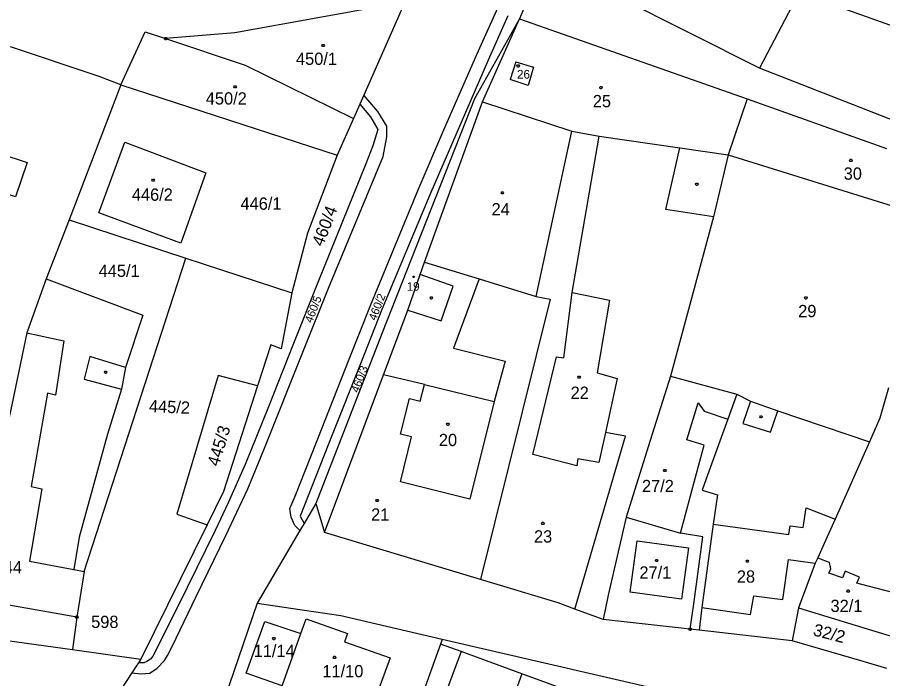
# Model space of a CAD drawing. Extents: x -634640 to -629202, y -1196156 to -1190068.
# Drawn here: x -631593.2 to -631473.2, y -1192521.9 to -1192430.1 of the extents above; entities that cross this region are included whole.
import ezdxf

# ---------------------------------------------------------------- set-up
doc = ezdxf.new("R2010")
doc.units = 0
for name, color, linetype in [('Vrstva 1', 7, 'Continuous'), ('Vrstva 2', 7, 'Continuous'), ('Vrstva 3', 7, 'Continuous'), ('Vrstva 4', 7, 'Continuous'), ('Vrstva 5', 7, 'Continuous'), ('Vrstva 8', 7, 'Continuous')]:
    doc.layers.add(name, color=color, linetype=linetype)

msp = doc.modelspace()

# ---------------------------------------------------------------- linework, layer by layer
at = {"layer": 'Vrstva 1'}
for p, q in [((-631490.28, -1192437.19), (-631513.73, -1192425.4)), ((-631539.49, -1192428.06), (-631563.09, -1192432.29)), ((-631539.49, -1192428.06), (-631545.2, -1192440.97)), ((-631522.44, -1192427.56), (-631523.59, -1192430.36)), ((-631470.93, -1192431.68), (-631480.78, -1192428.21)), ((-631529.49, -1192435.33), (-631526.57, -1192428.73)), ((-631485.75, -1192428.57), (-631490.28, -1192437.19)), ((-631523.59, -1192430.36), (-631529.85, -1192441.45)), ((-631528.71, -1192441.87), (-631523.59, -1192430.36)), ((-631525.2, -1192429.94), (-631527.92, -1192436.1)), ((-631523.59, -1192430.36), (-631492.01, -1192441.47)), ((-631563.09, -1192432.29), (-631572.7, -1192433.11)), ((-631581.89, -1192438.36), (-631594.19, -1192434.24)), ((-631534.08, -1192445.78), (-631529.49, -1192435.33)), ((-631527.92, -1192436.1), (-631536.04, -1192454.76)), ((-631524.11, -1192436.33), (-631524.88, -1192438.77)), ((-631524.11, -1192436.33), (-631521.67, -1192437.06)), ((-631521.67, -1192437.06), (-631522.4, -1192439.59)), ((-631456.75, -1192450.33), (-631490.28, -1192437.19)), ((-631578.89, -1192439.52), (-631581.89, -1192438.36)), ((-631522.4, -1192439.59), (-631524.88, -1192438.77)), ((-631578.89, -1192439.52), (-631586.04, -1192458.23)), ((-631578.89, -1192439.52), (-631548.87, -1192449.26)), ((-631545.2, -1192440.97), (-631545.75, -1192442.2)), ((-631543.24, -1192443.21), (-631545.2, -1192440.97)), ((-631545.75, -1192442.2), (-631546.62, -1192444.18)), ((-631545.75, -1192442.2), (-631544.26, -1192443.94)), ((-631529.85, -1192441.45), (-631542.64, -1192473.89)), ((-631536.75, -1192464.13), (-631528.71, -1192441.87)), ((-631528.71, -1192441.87), (-631516.35, -1192445.93)), ((-631492.01, -1192441.47), (-631494.64, -1192449.21)), ((-631492.01, -1192441.47), (-631472.67, -1192448.35)), ((-631541.98, -1192445.24), (-631543.24, -1192443.21)), ((-631546.62, -1192444.18), (-631548.87, -1192449.26)), ((-631544.26, -1192443.94), (-631543.25, -1192445.71)), ((-631543.25, -1192445.71), (-631543.95, -1192447.98)), ((-631542, -1192446.72), (-631541.98, -1192445.24)), ((-631537.66, -1192454.07), (-631534.08, -1192445.78)), ((-631521.26, -1192468.88), (-631516.35, -1192445.93)), ((-631516.35, -1192445.93), (-631512.53, -1192446.63)), ((-631542.51, -1192449.47), (-631542, -1192446.72)), ((-631516.28, -1192468.3), (-631512.53, -1192446.63)), ((-631512.53, -1192446.63), (-631501.33, -1192448.25)), ((-631581.93, -1192457.26), (-631578.31, -1192447.49)), ((-631578.31, -1192447.49), (-631567.08, -1192451.74)), ((-631543.95, -1192447.98), (-631544.92, -1192450.46)), ((-631501.33, -1192448.25), (-631494.64, -1192449.21)), ((-631548.87, -1192449.26), (-631552.99, -1192460.11)), ((-631550.08, -1192467.72), (-631542.51, -1192449.47)), ((-631494.64, -1192449.21), (-631496.68, -1192457.84)), ((-631494.64, -1192449.21), (-631462.58, -1192459.22)), ((-631544.92, -1192450.46), (-631551.55, -1192466.95)), ((-631567.08, -1192451.74), (-631570.56, -1192461.49)), ((-631544.24, -1192470.11), (-631537.66, -1192454.07)), ((-631536.04, -1192454.76), (-631542.7, -1192470.66)), ((-631586.04, -1192458.23), (-631589.23, -1192466.42)), ((-631586.04, -1192458.23), (-631569.85, -1192463.55)), ((-631570.56, -1192461.49), (-631581.93, -1192457.26)), ((-631496.68, -1192457.84), (-631502.65, -1192479.92)), ((-631552.99, -1192460.11), (-631555.16, -1192468.38)), ((-631583.95, -1192507.01), (-631569.85, -1192463.55)), ((-631569.85, -1192463.55), (-631555.16, -1192468.38)), ((-631537.37, -1192465.81), (-631536.75, -1192464.13)), ((-631536.75, -1192464.13), (-631529.19, -1192466.44)), ((-631589.23, -1192466.42), (-631591.94, -1192473.9)), ((-631589.23, -1192466.42), (-631575.84, -1192471.45)), ((-631539.1, -1192470.75), (-631537.37, -1192465.81)), ((-631529.19, -1192466.44), (-631532.74, -1192476.05)), ((-631529.19, -1192466.44), (-631521.26, -1192468.88)), ((-631551.55, -1192466.95), (-631555.01, -1192475.6)), ((-631553.45, -1192476.15), (-631550.08, -1192467.72)), ((-631555.16, -1192468.38), (-631556.66, -1192476.13)), ((-631521.26, -1192468.88), (-631519.36, -1192469.23)), ((-631517.46, -1192477.39), (-631516.28, -1192468.3)), ((-631547.2, -1192477.58), (-631544.24, -1192470.11)), ((-631519.36, -1192469.23), (-631528.98, -1192508.12)), ((-631575.84, -1192471.45), (-631578.23, -1192478.72)), ((-631542.7, -1192470.66), (-631545.65, -1192478.19)), ((-631542.46, -1192479.76), (-631539.1, -1192470.75)), ((-631591.94, -1192473.9), (-631599.64, -1192510.8)), ((-631542.64, -1192473.89), (-631551.83, -1192497.57)), ((-631558.1, -1192475.57), (-631559.93, -1192481.26)), ((-631559.04, -1192490.15), (-631553.45, -1192476.15)), ((-631555.01, -1192475.6), (-631558.41, -1192484.16)), ((-631556.66, -1192476.13), (-631558.1, -1192475.57)), ((-631532.74, -1192476.05), (-631525.58, -1192477.83)), ((-631521.76, -1192490.8), (-631518.44, -1192477.22)), ((-631518.44, -1192477.22), (-631517.46, -1192477.39)), ((-631551.05, -1192487.3), (-631547.2, -1192477.58)), ((-631545.65, -1192478.19), (-631549.56, -1192488.05)), ((-631525.58, -1192477.83), (-631527.12, -1192483.43)), ((-631578.23, -1192478.72), (-631578.79, -1192481.72)), ((-631565.39, -1192479.83), (-631571.12, -1192499.08)), ((-631559.93, -1192481.26), (-631565.39, -1192479.83)), ((-631550.62, -1192501.61), (-631542.46, -1192479.76)), ((-631536.77, -1192481.07), (-631542.46, -1192479.76)), ((-631502.65, -1192479.92), (-631505.46, -1192488.86)), ((-631502.65, -1192479.92), (-631493.46, -1192482.43)), ((-631578.79, -1192481.72), (-631580.75, -1192487.98)), ((-631559.93, -1192481.26), (-631564.65, -1192495.94)), ((-631537.35, -1192483.38), (-631536.77, -1192481.07)), ((-631472.4, -1192481.56), (-631473.59, -1192485.73)), ((-631540.1, -1192487.97), (-631538.85, -1192483.02)), ((-631538.85, -1192483.02), (-631537.35, -1192483.38)), ((-631527.12, -1192483.43), (-631530.5, -1192496.97)), ((-631493.46, -1192482.43), (-631494.7, -1192485.9)), ((-631493.46, -1192482.43), (-631491.57, -1192483.4)), ((-631491.57, -1192483.4), (-631487.74, -1192484.75)), ((-631558.41, -1192484.16), (-631561.63, -1192492.19)), ((-631487.74, -1192484.75), (-631475.05, -1192489.01)), ((-631473.59, -1192485.73), (-631475.05, -1192489.01)), ((-631494.7, -1192485.9), (-631497.69, -1192494.16)), ((-631580.75, -1192487.98), (-631584.65, -1192502.24)), ((-631554.7, -1192496.56), (-631551.05, -1192487.3)), ((-631549.56, -1192488.05), (-631554.02, -1192499.34)), ((-631538.57, -1192488.33), (-631540.1, -1192487.97)), ((-631515.9, -1192512.23), (-631508.89, -1192488.24)), ((-631511.68, -1192487.73), (-631512.58, -1192491.9)), ((-631508.89, -1192488.24), (-631511.68, -1192487.73)), ((-631540.11, -1192494.56), (-631538.57, -1192488.33)), ((-631505.46, -1192488.86), (-631508.79, -1192499.48)), ((-631475.05, -1192489.01), (-631479.83, -1192499.76)), ((-631561.29, -1192495.55), (-631559.04, -1192490.15)), ((-631515.65, -1192492.35), (-631521.76, -1192490.8)), ((-631515.49, -1192491.41), (-631515.65, -1192492.35)), ((-631512.58, -1192491.9), (-631515.49, -1192491.41)), ((-631561.63, -1192492.19), (-631563.99, -1192497.47)), ((-631497.69, -1192494.16), (-631498.26, -1192495.72)), ((-631530.5, -1192496.97), (-631540.11, -1192494.56)), ((-631564.65, -1192495.94), (-631566.93, -1192500.56)), ((-631564.32, -1192502.02), (-631561.29, -1192495.55)), ((-631555.46, -1192498.27), (-631554.7, -1192496.56)), ((-631498.26, -1192495.72), (-631496.14, -1192496.39)), ((-631496.14, -1192496.39), (-631496.72, -1192500.46)), ((-631563.99, -1192497.47), (-631565.82, -1192501.31)), ((-631551.83, -1192497.57), (-631553.46, -1192500.34)), ((-631551.83, -1192497.57), (-631550.62, -1192501.61)), ((-631555.27, -1192499.5), (-631555.46, -1192498.27)), ((-631571.12, -1192499.08), (-631566.93, -1192500.56)), ((-631554.75, -1192500.65), (-631555.27, -1192499.5)), ((-631554.02, -1192499.34), (-631553.46, -1192500.34)), ((-631508.79, -1192499.48), (-631511.31, -1192510.28)), ((-631508.79, -1192499.48), (-631501.28, -1192501.7)), ((-631479.83, -1192499.76), (-631481.34, -1192503.14)), ((-631566.93, -1192500.56), (-631576.09, -1192519.16)), ((-631565.82, -1192501.31), (-631570.97, -1192511.89)), ((-631554.05, -1192501.34), (-631559.96, -1192511.39)), ((-631554.05, -1192501.34), (-631554.75, -1192500.65)), ((-631553.46, -1192500.34), (-631554.05, -1192501.34)), ((-631496.72, -1192500.46), (-631498.3, -1192512.01)), ((-631584.65, -1192502.24), (-631585.42, -1192506.74)), ((-631568.43, -1192510.5), (-631564.32, -1192502.02)), ((-631528.98, -1192508.12), (-631550.62, -1192501.61)), ((-631481.34, -1192503.14), (-631482.23, -1192505.14)), ((-631482.56, -1192505.88), (-631484.9, -1192512.07)), ((-631482.23, -1192505.14), (-631482.56, -1192505.88)), ((-631585.42, -1192506.74), (-631583.95, -1192507.01)), ((-631583.95, -1192507.01), (-631585, -1192513.33)), ((-631518.24, -1192511.36), (-631528.98, -1192508.12)), ((-631571.77, -1192517.4), (-631568.43, -1192510.5)), ((-631511.31, -1192510.28), (-631511.98, -1192513.68)), ((-631570.97, -1192511.89), (-631574.43, -1192518.77)), ((-631559.96, -1192511.39), (-631565.82, -1192528.47)), ((-631559.96, -1192511.39), (-631554.07, -1192512.29)), ((-631515.9, -1192512.23), (-631518.24, -1192511.36)), ((-631511.98, -1192513.68), (-631515.9, -1192512.23)), ((-631499.93, -1192515.03), (-631499.35, -1192511.19)), ((-631498.3, -1192512.01), (-631498.69, -1192515.17)), ((-631484.9, -1192512.07), (-631485.75, -1192516.61)), ((-631484.9, -1192512.07), (-631474.77, -1192515.13)), ((-631585, -1192513.33), (-631585.57, -1192517.83)), ((-631554.07, -1192512.29), (-631548.36, -1192513.13)), ((-631548.36, -1192513.13), (-631534.3, -1192516.38)), ((-631561.49, -1192521.13), (-631558.9, -1192513.95)), ((-631558.9, -1192513.95), (-631553.93, -1192515.63)), ((-631553.93, -1192515.63), (-631553.19, -1192513.56)), ((-631553.19, -1192513.56), (-631547.44, -1192515.61)), ((-631499.93, -1192515.03), (-631511.98, -1192513.68)), ((-631600.91, -1192515.76), (-631585.57, -1192517.83)), ((-631556.51, -1192522.86), (-631553.93, -1192515.63)), ((-631547.44, -1192515.61), (-631547.85, -1192516.75)), ((-631498.69, -1192515.17), (-631499.93, -1192515.03)), ((-631485.75, -1192516.61), (-631498.69, -1192515.17)), ((-631474.77, -1192515.13), (-631471.87, -1192516.01)), ((-631547.85, -1192516.75), (-631541.51, -1192519)), ((-631534.3, -1192516.38), (-631534.56, -1192517.11)), ((-631534.3, -1192516.38), (-631497.57, -1192524.88)), ((-631476.38, -1192519.35), (-631485.75, -1192516.61)), ((-631585.57, -1192517.83), (-631576.09, -1192519.16)), ((-631572.41, -1192518.66), (-631571.77, -1192517.4)), ((-631534.56, -1192517.11), (-631541.55, -1192536.43)), ((-631531.67, -1192518.13), (-631536.24, -1192530.34)), ((-631531.67, -1192518.13), (-631534.56, -1192517.11)), ((-631523.28, -1192521.21), (-631531.67, -1192518.13)), ((-631576.09, -1192519.16), (-631576.44, -1192519.7)), ((-631574.78, -1192519.17), (-631575.26, -1192519.51)), ((-631574.43, -1192518.77), (-631574.78, -1192519.17)), ((-631573.87, -1192520.42), (-631572.83, -1192519.35)), ((-631572.83, -1192519.35), (-631572.41, -1192518.66)), ((-631541.51, -1192519), (-631544.51, -1192527.15)), ((-631472.64, -1192520.48), (-631476.38, -1192519.35)), ((-631576.75, -1192520.16), (-631577.34, -1192521.05)), ((-631576.44, -1192519.7), (-631576.75, -1192520.16)), ((-631575.69, -1192519.66), (-631576.44, -1192519.7)), ((-631575.26, -1192519.51), (-631575.69, -1192519.66)), ((-631574.86, -1192521.11), (-631573.87, -1192520.42)), ((-631577.34, -1192521.05), (-631580.95, -1192526.53)), ((-631577.34, -1192521.05), (-631576.05, -1192521.2)), ((-631576.05, -1192521.2), (-631574.86, -1192521.11)), ((-631556.51, -1192522.86), (-631561.49, -1192521.13)), ((-631523.28, -1192521.21), (-631527.71, -1192533.42)), ((-631515.39, -1192524.08), (-631523.28, -1192521.21))]:
    msp.add_line(p, q, dxfattribs=at)
for points in [[(-631578.89, -1192439.52), (-631575.53, -1192432.16), (-631572.7, -1192433.11)], [(-631572.7, -1192433.11), (-631561.66, -1192436.8), (-631546.62, -1192444.18)], [(-631597.29, -1192453.81), (-631595.7, -1192449.03), (-631591.88, -1192450.3), (-631593.51, -1192455.07), (-631597.29, -1192453.81)], [(-631499.35, -1192511.19), (-631498.15, -1192502.2), (-631501.28, -1192501.7)]]:
    msp.add_lwpolyline(points, dxfattribs=at)
at = {"layer": 'Vrstva 3'}
for points in [[(-631550.75, -1192433.9), (-631550.66, -1192434.05), (-631550.75, -1192434.2), (-631550.93, -1192434.2), (-631551.02, -1192434.05), (-631550.93, -1192433.9), (-631550.75, -1192433.9)], [(-631562.95, -1192439.65), (-631562.86, -1192439.8), (-631562.95, -1192439.95), (-631563.13, -1192439.95), (-631563.22, -1192439.8), (-631563.13, -1192439.65), (-631562.95, -1192439.65)], [(-631512.2, -1192439.75), (-631512.11, -1192439.9), (-631512.2, -1192440.05), (-631512.38, -1192440.05), (-631512.47, -1192439.9), (-631512.38, -1192439.75), (-631512.2, -1192439.75)], [(-631477.53, -1192449.84), (-631477.44, -1192449.99), (-631477.53, -1192450.14), (-631477.71, -1192450.14), (-631477.8, -1192449.99), (-631477.71, -1192449.84), (-631477.53, -1192449.84)], [(-631525.88, -1192454.34), (-631525.79, -1192454.49), (-631525.88, -1192454.64), (-631526.06, -1192454.64), (-631526.15, -1192454.49), (-631526.06, -1192454.34), (-631525.88, -1192454.34)], [(-631538.22, -1192466.05), (-631538.159, -1192466.15), (-631538.22, -1192466.25), (-631538.34, -1192466.25), (-631538.401, -1192466.15), (-631538.34, -1192466.05), (-631538.22, -1192466.05)], [(-631483.78, -1192468.92), (-631483.69, -1192469.07), (-631483.78, -1192469.22), (-631483.96, -1192469.22), (-631484.05, -1192469.07), (-631483.96, -1192468.92), (-631483.78, -1192468.92)], [(-631543.26, -1192497.02), (-631543.17, -1192497.17), (-631543.26, -1192497.32), (-631543.44, -1192497.32), (-631543.53, -1192497.17), (-631543.44, -1192497.02), (-631543.26, -1192497.02)], [(-631520.25, -1192500.19), (-631520.16, -1192500.34), (-631520.25, -1192500.49), (-631520.43, -1192500.49), (-631520.52, -1192500.34), (-631520.43, -1192500.19), (-631520.25, -1192500.19)]]:
    msp.add_lwpolyline(points, dxfattribs=at)
at = {"layer": 'Vrstva 4'}
for p, q in [((-631503.28, -1192456.81), (-631501.33, -1192448.25)), ((-631496.68, -1192457.84), (-631503.28, -1192456.81)), ((-631532.79, -1192467.44), (-631537.37, -1192465.81)), ((-631534.45, -1192472.23), (-631532.79, -1192467.44)), ((-631516.28, -1192468.3), (-631511.1, -1192469.39)), ((-631511.1, -1192469.39), (-631512.8, -1192479.48)), ((-631539.1, -1192470.75), (-631534.45, -1192472.23)), ((-631591.94, -1192473.9), (-631586.78, -1192475.03)), ((-631586.78, -1192475.03), (-631587.93, -1192482.54)), ((-631583.19, -1192477.19), (-631583.98, -1192480.33)), ((-631578.23, -1192478.72), (-631583.19, -1192477.19)), ((-631512.8, -1192479.48), (-631510.05, -1192480.23)), ((-631583.98, -1192480.33), (-631578.79, -1192481.72)), ((-631510.05, -1192480.23), (-631511.68, -1192487.73)), ((-631536.77, -1192481.07), (-631527.12, -1192483.43)), ((-631589.04, -1192482.26), (-631591.32, -1192495.24)), ((-631587.93, -1192482.54), (-631589.04, -1192482.26)), ((-631491.57, -1192483.4), (-631492.63, -1192486.49)), ((-631500.38, -1192488.76), (-631498.83, -1192483.63)), ((-631498.83, -1192483.63), (-631497.96, -1192484.8)), ((-631497.96, -1192484.8), (-631494.7, -1192485.9)), ((-631488.76, -1192487.68), (-631487.74, -1192484.75)), ((-631492.63, -1192486.49), (-631488.76, -1192487.68)), ((-631497.98, -1192489.49), (-631500.38, -1192488.76)), ((-631499.18, -1192493.95), (-631497.98, -1192489.49)), ((-631501.28, -1192501.7), (-631499.18, -1192493.95)), ((-631591.32, -1192495.24), (-631589.86, -1192495.55)), ((-631589.86, -1192495.55), (-631591.54, -1192505.59)), ((-631484.24, -1192500.9), (-631483.81, -1192498.2)), ((-631483.81, -1192498.2), (-631479.83, -1192499.76)), ((-631496.72, -1192500.46), (-631486.23, -1192501.9)), ((-631486.23, -1192501.9), (-631486.05, -1192500.7)), ((-631486.05, -1192500.7), (-631484.24, -1192500.9)), ((-631591.54, -1192505.59), (-631585.42, -1192506.74)), ((-631487.07, -1192510.9), (-631486.28, -1192505.37)), ((-631486.28, -1192505.37), (-631482.56, -1192505.88)), ((-631481.59, -1192505.38), (-631482.23, -1192505.14)), ((-631476.29, -1192508.78), (-631476.78, -1192508.65)), ((-631470.36, -1192510.33), (-631476.29, -1192508.78)), ((-631585, -1192513.33), (-631599.64, -1192510.8)), ((-631491.54, -1192513), (-631491.08, -1192510.39)), ((-631491.08, -1192510.39), (-631487.07, -1192510.9)), ((-631498.3, -1192512.01), (-631491.54, -1192513))]:
    msp.add_line(p, q, dxfattribs=at)
for points in [[(-631500.13, -1192503.72), (-631501.12, -1192510.84), (-631508.23, -1192509.86), (-631507.28, -1192502.74), (-631500.13, -1192503.72)], [(-631480.67, -1192507.26), (-631480.42, -1192506.65), (-631480.59, -1192505.76), (-631481.59, -1192505.38)], [(-631478.43, -1192506.96), (-631478.77, -1192507.9), (-631480.67, -1192507.26)], [(-631476.78, -1192508.65), (-631476.41, -1192507.78), (-631478.43, -1192506.96)]]:
    msp.add_lwpolyline(points, dxfattribs=at)
at = {"layer": 'Vrstva 5'}
for points in [[(-631523.67, -1192436.75), (-631523.58, -1192436.9), (-631523.67, -1192437.05), (-631523.85, -1192437.05), (-631523.94, -1192436.9), (-631523.85, -1192436.75), (-631523.67, -1192436.75)], [(-631574.3, -1192452.58), (-631574.21, -1192452.73), (-631574.3, -1192452.88), (-631574.48, -1192452.88), (-631574.57, -1192452.73), (-631574.48, -1192452.58), (-631574.3, -1192452.58)], [(-631498.92, -1192453.16), (-631498.83, -1192453.31), (-631498.92, -1192453.46), (-631499.1, -1192453.46), (-631499.19, -1192453.31), (-631499.1, -1192453.16), (-631498.92, -1192453.16)], [(-631535.73, -1192468.92), (-631535.64, -1192469.07), (-631535.73, -1192469.22), (-631535.91, -1192469.22), (-631536, -1192469.07), (-631535.91, -1192468.92), (-631535.73, -1192468.92)], [(-631580.9, -1192479.23), (-631580.81, -1192479.38), (-631580.9, -1192479.53), (-631581.08, -1192479.53), (-631581.17, -1192479.38), (-631581.08, -1192479.23), (-631580.9, -1192479.23)], [(-631515.24, -1192479.92), (-631515.15, -1192480.07), (-631515.24, -1192480.22), (-631515.42, -1192480.22), (-631515.51, -1192480.07), (-631515.42, -1192479.92), (-631515.24, -1192479.92)], [(-631490, -1192485.42), (-631489.91, -1192485.57), (-631490, -1192485.72), (-631490.18, -1192485.72), (-631490.27, -1192485.57), (-631490.18, -1192485.42), (-631490, -1192485.42)], [(-631533.43, -1192486.45), (-631533.34, -1192486.6), (-631533.43, -1192486.75), (-631533.61, -1192486.75), (-631533.7, -1192486.6), (-631533.61, -1192486.45), (-631533.43, -1192486.45)], [(-631503.34, -1192492.86), (-631503.25, -1192493.01), (-631503.34, -1192493.16), (-631503.52, -1192493.16), (-631503.61, -1192493.01), (-631503.52, -1192492.86), (-631503.34, -1192492.86)], [(-631504.48, -1192505.33), (-631504.39, -1192505.48), (-631504.48, -1192505.63), (-631504.66, -1192505.63), (-631504.75, -1192505.48), (-631504.66, -1192505.33), (-631504.48, -1192505.33)], [(-631491.9, -1192505.44), (-631491.81, -1192505.59), (-631491.9, -1192505.74), (-631492.08, -1192505.74), (-631492.17, -1192505.59), (-631492.08, -1192505.44), (-631491.9, -1192505.44)], [(-631477.91, -1192509.58), (-631477.82, -1192509.73), (-631477.91, -1192509.88), (-631478.09, -1192509.88), (-631478.18, -1192509.73), (-631478.09, -1192509.58), (-631477.91, -1192509.58)], [(-631557.57, -1192516.17), (-631557.48, -1192516.32), (-631557.57, -1192516.47), (-631557.75, -1192516.47), (-631557.84, -1192516.32), (-631557.75, -1192516.17), (-631557.57, -1192516.17)], [(-631549.15, -1192518.78), (-631549.06, -1192518.93), (-631549.15, -1192519.08), (-631549.33, -1192519.08), (-631549.42, -1192518.93), (-631549.33, -1192518.78), (-631549.15, -1192518.78)]]:
    msp.add_lwpolyline(points, dxfattribs=at)
at = {"layer": 'Vrstva 8'}
for points in [[(-631572.61, -1192432.96), (-631572.52, -1192433.11), (-631572.61, -1192433.26), (-631572.79, -1192433.26), (-631572.88, -1192433.11), (-631572.79, -1192432.96), (-631572.61, -1192432.96)], [(-631584.91, -1192513.18), (-631584.82, -1192513.33), (-631584.91, -1192513.48), (-631585.09, -1192513.48), (-631585.18, -1192513.33), (-631585.09, -1192513.18), (-631584.91, -1192513.18)], [(-631499.84, -1192514.88), (-631499.75, -1192515.03), (-631499.84, -1192515.18), (-631500.02, -1192515.18), (-631500.11, -1192515.03), (-631500.02, -1192514.88), (-631499.84, -1192514.88)]]:
    msp.add_lwpolyline(points, dxfattribs=at)

# ---------------------------------------------------------------- texts
at = {"layer": 'Vrstva 2'}
for s, height, p in [('450/1', 1.7, (-631554.594, -1192436.75)), ('26', 1.2, (-631523.932, -1192438.65)), ('450/2', 1.7, (-631567.102, -1192442.25)), ('25', 1.7, (-631513.423, -1192442.62)), ('30', 1.7, (-631478.623, -1192452.67)), ('446/2', 1.7, (-631577.363, -1192455.59)), ('446/1', 1.7, (-631562.293, -1192456.84)), ('24', 1.7, (-631527.463, -1192457.62)), ('445/1', 1.7, (-631581.963, -1192466.16)), ('19', 1.19, (-631539.225, -1192468.08)), ('29', 1.7, (-631484.933, -1192471.74)), ('22', 1.7, (-631516.503, -1192483.07)), ('20', 1.7, (-631534.773, -1192489.62)), ('27/2', 1.7, (-631506.605, -1192496.01)), ('21', 1.7, (-631544.173, -1192499.96)), ('23', 1.7, (-631521.583, -1192503)), ('444', 1.7, (-631596.393, -1192507.28)), ('27/1', 1.7, (-631506.957, -1192508)), ('28', 1.7, (-631493.443, -1192508.56)), ('32/1', 1.7, (-631480.453, -1192512.63)), ('11/14', 1.7, (-631560.464, -1192518.88)), ('11/10', 1.7, (-631550.937, -1192521.69))]:
    msp.add_text(s, height=height, dxfattribs=at).set_placement(p)
for s, height, rotation, p in [('460/4', 1.7, 68.86953, (-631550.864, -1192462.039)), ('460/5', 1.14, 68.86953, (-631552.373, -1192472.622)), ('460/2', 1.14, 68.86953, (-631543.513, -1192472.302)), ('460/3', 1.14, 68.86953, (-631545.943, -1192482.302)), ('445/2', 1.7, 357.58296, (-631575.013, -1192484.91)), ('445/3', 1.7, 73.16671, (-631565.311, -1192492.543)), ('32/2', 1.7, 345.55085, (-631482.97, -1192515.859))]:
    msp.add_text(s, height=height, rotation=rotation, dxfattribs=at).set_placement(p)
at = {"layer": 'Vrstva 8'}
msp.add_text('598', height=1.7, dxfattribs=at).set_placement((-631583.003, -1192514.85))

doc.saveas('drawing.dxf')
